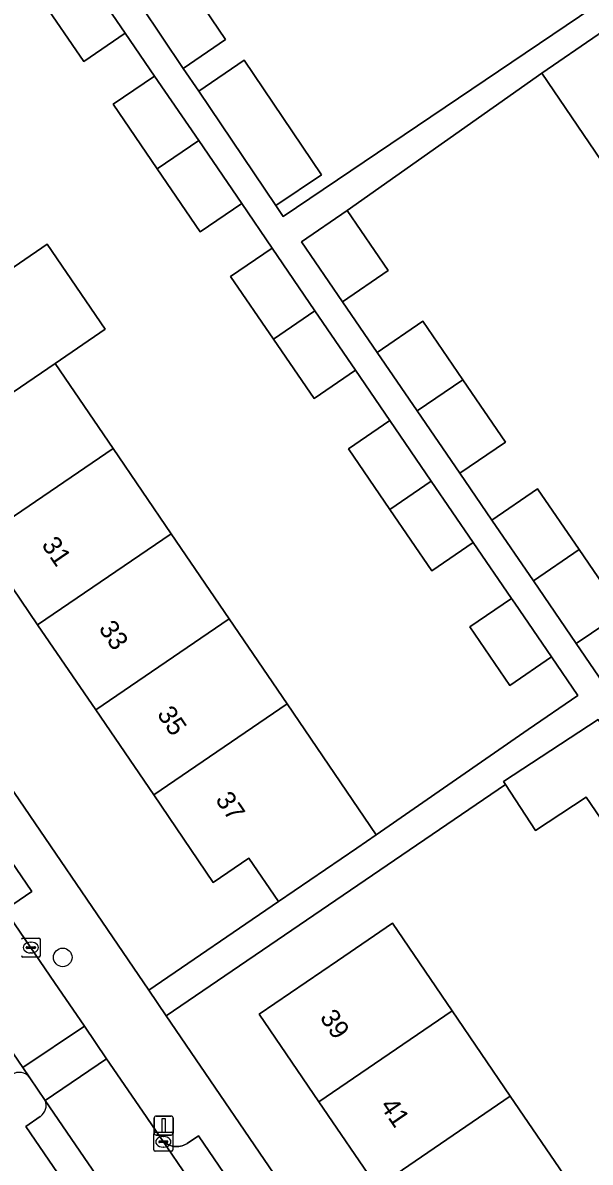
# Model space of a CAD drawing. Extents: x 157445 to 158888, y 383061 to 384688.
# Drawn here: x 158247.8 to 158277.7, y 383793.9 to 383854 of the extents above; entities that cross this region are included whole.
import ezdxf

# ---------------------------------------------------------------- set-up
doc = ezdxf.new("R2010")
doc.units = 0
for name, color, linetype in [('IMGEO_Boom', 7, 'Continuous'), ('IMGEO_Erf', 7, 'Continuous'), ('IMGEO_Kolk', 7, 'Continuous'), ('IMGEO_Lichtmast', 7, 'Continuous'), ('IMGEO_Pand', 7, 'Continuous'), ('IMGEO_Pand_nummerreeks', 7, 'Continuous'), ('IMGEO_Parkeervlak_open', 7, 'Continuous'), ('IMGEO_Rijbaan_lokaal_open', 7, 'Continuous'), ('IMGEO_Voetpad_open', 7, 'Continuous')]:
    doc.layers.add(name, color=color, linetype=linetype)

msp = doc.modelspace()

# ---------------------------------------------------------------- linework, layer by layer
at = {"layer": 'IMGEO_Boom'}
msp.add_circle((158249.88, 383804.706), 0.489, dxfattribs=at)
at = {"layer": 'IMGEO_Erf'}
for points in [[(158238.26, 383864.78), (158220.561, 383852.622), (158254.415, 383802.985), (158261.257, 383807.652), (158259.697, 383809.94), (158257.824, 383808.662), (158254.679, 383813.274), (158251.618, 383817.762), (158248.556, 383822.251), (158245.495, 383826.74), (158242.434, 383831.228), (158239.373, 383835.717), (158236.312, 383840.206), (158233.251, 383844.694), (158230.19, 383849.182), (158227.044, 383853.795), (158231.175, 383856.612)], [(158256.249, 383856.407), (158258.471, 383853.116), (158256.237, 383851.592), (158257.054, 383850.382), (158259.458, 383852.022), (158263.537, 383845.982), (158261.125, 383844.354), (158261.51, 383843.785), (158282.821, 383858.177)], [(158246.411, 383840.515), (158249.066, 383842.326), (158252.127, 383837.837), (158249.472, 383836.027), (158252.532, 383831.539), (158255.594, 383827.05), (158258.655, 383822.561), (158261.716, 383818.073), (158266.421, 383811.174), (158274.432, 383816.734), (158277.048, 383818.521), (158275.661, 383820.551), (158273.47, 383819.055), (158271.361, 383822.144), (158273.552, 383823.637), (158271.536, 383826.587), (158269.345, 383825.094), (158267.136, 383828.327), (158264.948, 383831.53), (158267.137, 383833.023), (158265.327, 383835.672), (158263.138, 383834.179), (158261, 383837.308), (158258.739, 383840.618), (158260.928, 383842.111), (158259.321, 383844.463), (158257.132, 383842.97), (158254.864, 383846.29), (158252.536, 383849.696), (158254.724, 383851.189), (158253.179, 383853.45), (158250.991, 383851.958), (158248.728, 383855.27)], [(158278.293, 383846.731), (158275.149, 383851.338), (158264.887, 383844.101), (158267.053, 383840.934), (158264.642, 383839.288), (158266.476, 383836.608), (158268.887, 383838.254), (158270.993, 383835.175), (158273.246, 383831.882), (158270.834, 383830.236), (158272.522, 383827.767), (158274.935, 383829.413), (158277.126, 383826.21), (158279.388, 383822.904), (158276.975, 383821.258), (158278.641, 383818.821)], [(158279.716, 383788.261), (158289.804, 383795.148), (158287.528, 383798.479), (158289.419, 383799.768), (158289.706, 383799.964), (158287.94, 383802.549), (158285.762, 383801.064), (158283.578, 383804.261), (158281.243, 383807.679), (158283.42, 383809.165), (158281.992, 383811.358), (158279.766, 383809.84), (158277.501, 383813.155), (158274.827, 383811.404), (158273.238, 383813.832), (158255.342, 383801.626), (158269.302, 383781.158)], [(158266.462, 383792.588), (158263.394, 383797.087), (158260.24, 383801.712), (158264.371, 383804.53), (158267.272, 383806.508), (158270.426, 383801.884), (158273.494, 383797.384), (158276.563, 383792.885)]]:
    msp.add_lwpolyline(points, dxfattribs=at)
at = {"layer": 'IMGEO_Kolk'}
for p, q in [((158247.772, 383805.725), (158248.624, 383805.725)), ((158248.185, 383805.505), (158248.21, 383805.505)), ((158248.698, 383805.651), (158248.698, 383804.799)), ((158248.624, 383804.725), (158247.772, 383804.725)), ((158247.956, 383805.219), (158247.956, 383805.231)), ((158248.394, 383805.182), (158247.996, 383805.182)), ((158247.999, 383805.268), (158248.397, 383805.268)), ((158248.208, 383804.945), (158248.183, 383804.945)), ((158248.44, 383805.231), (158248.44, 383805.219)), ((158254.687, 383794.556), (158254.687, 383795.408)), ((158254.762, 383795.482), (158255.614, 383795.482)), ((158255.175, 383795.262), (158255.2, 383795.262)), ((158255.688, 383795.408), (158255.688, 383794.556)), ((158254.946, 383794.976), (158254.946, 383794.988)), ((158255.384, 383794.939), (158254.986, 383794.939)), ((158254.989, 383795.025), (158255.387, 383795.025)), ((158255.198, 383794.702), (158255.173, 383794.702)), ((158255.43, 383794.988), (158255.43, 383794.976)), ((158255.614, 383794.482), (158254.762, 383794.482))]:
    msp.add_line(p, q, dxfattribs=at)
for points in [[(158247.772, 383805.725), (158248.624, 383805.725)], [(158248.698, 383805.651), (158248.698, 383804.799)], [(158248.624, 383804.725), (158247.772, 383804.725)], [(158254.687, 383794.556), (158254.687, 383795.408)], [(158254.762, 383795.482), (158255.614, 383795.482)], [(158255.688, 383795.408), (158255.688, 383794.556)], [(158255.614, 383794.482), (158254.762, 383794.482)]]:
    msp.add_lwpolyline(points, dxfattribs=at)
for centre, radius, start, end in [((158247.774, 383805.649), 0.0765, 91.55205, 178.44795), ((158247.774, 383805.649), 0.0765, 91.55205, 178.44795), ((158248.622, 383805.649), 0.0765, 1.55205, 88.44795), ((158248.622, 383805.649), 0.0765, 1.55205, 88.44795), ((158247.774, 383804.801), 0.0765, 181.55205, 268.44795), ((158247.774, 383804.801), 0.0765, 181.55205, 268.44795), ((158247.996, 383805.228), 0.0403, 85.87752, 175.75265), ((158247.993, 383805.218), 0.0366, 178.93798, 274.71019), ((158248.397, 383805.225), 0.043, 264.86636, 352.45326), ((158248.401, 383805.23), 0.0386, 1.73085, 96.63898), ((158248.622, 383804.801), 0.0765, 271.55205, 358.44795), ((158248.622, 383804.801), 0.0765, 271.55205, 358.44795), ((158254.764, 383795.406), 0.0765, 91.55205, 178.44795), ((158254.764, 383795.406), 0.0765, 91.55205, 178.44795), ((158255.612, 383795.406), 0.0765, 1.55205, 88.44795), ((158255.612, 383795.406), 0.0765, 1.55205, 88.44795), ((158254.764, 383794.558), 0.0765, 181.55205, 268.44795), ((158254.764, 383794.558), 0.0765, 181.55205, 268.44795), ((158254.986, 383794.985), 0.0403, 85.87752, 175.75265), ((158254.983, 383794.975), 0.0366, 178.93798, 274.71019), ((158255.387, 383794.982), 0.043, 264.86636, 352.45326), ((158255.391, 383794.987), 0.0386, 1.73085, 96.63898), ((158255.612, 383794.558), 0.0765, 271.55205, 358.44795), ((158255.612, 383794.558), 0.0765, 271.55205, 358.44795)]:
    msp.add_arc(centre, radius, start, end, dxfattribs=at)
for centre, major_axis, ratio, start_param, end_param in [((158248.184, 383805.225), (-0.387, 0.002), 0.722429, 4.712389, 7.853982), ((158248.209, 383805.225), (-0.39, 0.002), 0.717154, 1.570796, 4.712389), ((158255.174, 383794.982), (-0.387, 0.002), 0.722429, 4.712389, 7.853982), ((158255.199, 383794.982), (-0.39, 0.002), 0.717154, 1.570796, 4.712389)]:
    msp.add_ellipse(centre, major_axis=major_axis, ratio=ratio, start_param=start_param, end_param=end_param, dxfattribs=at)
at = {"layer": 'IMGEO_Lichtmast'}
for p, q in [((158254.809, 383796.34), (158255.599, 383796.34)), ((158255.599, 383796.34), (158254.809, 383796.34)), ((158254.709, 383795.44), (158254.709, 383796.24)), ((158254.709, 383796.24), (158254.709, 383795.44)), ((158255.699, 383796.24), (158255.699, 383795.44)), ((158255.699, 383795.44), (158255.699, 383796.24)), ((158255.599, 383795.34), (158254.809, 383795.34)), ((158254.809, 383795.34), (158255.599, 383795.34))]:
    msp.add_line(p, q, dxfattribs=at)
msp.add_lwpolyline([(158255.129, 383796.215), (158255.279, 383796.215), (158255.279, 383795.465), (158255.129, 383795.465), (158255.129, 383796.215)], dxfattribs=at)
for centre, start, end in [((158254.809, 383796.24), 90, 180), ((158254.809, 383796.24), 90, 180), ((158255.599, 383796.24), 0, 90), ((158255.599, 383796.24), 360, 90), ((158254.809, 383795.44), 180, 270), ((158254.809, 383795.44), 180, 270), ((158255.599, 383795.44), 270, 0), ((158255.599, 383795.44), 270, 0)]:
    msp.add_arc(centre, 0.1, start, end, dxfattribs=at)
at = {"layer": 'IMGEO_Pand'}
for points in [[(158250.916, 383856.762), (158248.728, 383855.27), (158250.991, 383851.958), (158253.179, 383853.45)], [(158256.249, 383856.407), (158254.015, 383854.882), (158256.237, 383851.592), (158258.471, 383853.116)], [(158278.293, 383846.731), (158285.41, 383851.588), (158282.267, 383856.195), (158278.137, 383853.377), (158275.149, 383851.338)], [(158259.458, 383852.022), (158257.054, 383850.382), (158261.125, 383844.354), (158263.537, 383845.982)], [(158254.724, 383851.189), (158252.536, 383849.696), (158254.864, 383846.29), (158257.052, 383847.782)], [(158257.052, 383847.782), (158254.864, 383846.29), (158257.132, 383842.97), (158259.321, 383844.463)], [(158264.887, 383844.101), (158262.478, 383842.453), (158264.642, 383839.288), (158267.053, 383840.934)], [(158252.127, 383837.837), (158249.066, 383842.326), (158246.411, 383840.515), (158239.373, 383835.717), (158242.434, 383831.228), (158249.472, 383836.027)], [(158260.928, 383842.111), (158258.739, 383840.618), (158261, 383837.308), (158263.189, 383838.801)], [(158263.189, 383838.801), (158261, 383837.308), (158263.138, 383834.179), (158265.327, 383835.672)], [(158266.476, 383836.608), (158268.581, 383833.529), (158270.993, 383835.175), (158268.887, 383838.254)], [(158249.472, 383836.027), (158242.434, 383831.228), (158245.495, 383826.74), (158252.532, 383831.539)], [(158270.993, 383835.175), (158268.581, 383833.529), (158270.834, 383830.236), (158273.246, 383831.882)], [(158267.137, 383833.023), (158264.948, 383831.53), (158267.136, 383828.327), (158269.326, 383829.821)], [(158252.532, 383831.539), (158245.495, 383826.74), (158248.556, 383822.251), (158255.594, 383827.05)], [(158269.326, 383829.821), (158267.136, 383828.327), (158269.345, 383825.094), (158271.536, 383826.587)], [(158272.522, 383827.767), (158274.713, 383824.564), (158277.126, 383826.21), (158274.935, 383829.413)], [(158255.594, 383827.05), (158248.556, 383822.251), (158251.618, 383817.762), (158258.655, 383822.561)], [(158277.126, 383826.21), (158274.713, 383824.564), (158276.975, 383821.258), (158279.388, 383822.904)], [(158273.728, 383823.38), (158273.552, 383823.637), (158271.361, 383822.144), (158273.47, 383819.055), (158275.661, 383820.551)], [(158254.679, 383813.274), (158261.716, 383818.073), (158258.655, 383822.561), (158251.618, 383817.762)], [(158254.679, 383813.274), (158257.824, 383808.662), (158259.697, 383809.94), (158261.257, 383807.652), (158265.388, 383810.47), (158266.421, 383811.174), (158261.716, 383818.073)], [(158273.136, 383813.988), (158273.238, 383813.832), (158274.827, 383811.404), (158277.501, 383813.155), (158279.766, 383809.84), (158281.992, 383811.358), (158278.13, 383817.257)], [(158270.426, 383801.884), (158267.272, 383806.508), (158264.371, 383804.53), (158260.24, 383801.712), (158263.394, 383797.087)], [(158266.462, 383792.588), (158273.494, 383797.384), (158270.426, 383801.884), (158263.394, 383797.087)], [(158269.531, 383788.089), (158276.563, 383792.885), (158273.494, 383797.384), (158266.462, 383792.588)]]:
    msp.add_lwpolyline(points, close=True, dxfattribs=at)
at = {"layer": 'IMGEO_Parkeervlak_open'}
for points in [[(158248.151, 383798.359), (158247.776, 383798.907), (158231.849, 383822.216)], [(158247.246, 383807.504), (158248.248, 383808.187), (158238.955, 383821.804)], [(158262.112, 383777.939), (158248.949, 383797.166)], [(158248.698, 383796.319), (158247.928, 383795.793), (158260.491, 383777.419), (158261.427, 383778.057)], [(158266.338, 383781.661), (158257.041, 383795.301), (158256.452, 383794.9), (158256.422, 383794.88), (158256.344, 383794.836), (158256.263, 383794.799), (158256.179, 383794.769), (158256.092, 383794.747), (158256.003, 383794.733), (158255.914, 383794.726), (158255.825, 383794.728), (158255.736, 383794.738), (158255.648, 383794.755), (158255.562, 383794.78), (158255.479, 383794.813), (158255.399, 383794.854), (158255.323, 383794.901), (158255.251, 383794.955), (158255.185, 383795.014), (158255.124, 383795.08), (158255.069, 383795.151), (158265.297, 383780.146)]]:
    msp.add_lwpolyline(points, dxfattribs=at)
for centre, radius, start, end in [((158247.587, 383797.943), 0.701, 36.41426, 124.29313), ((158248.303, 383796.897), 0.7, 304.37226, 22.61441)]:
    msp.add_arc(centre, radius, start, end, dxfattribs=at)
at = {"layer": 'IMGEO_Rijbaan_lokaal_open'}
for points in [[(158247.776, 383798.907), (158251.028, 383801.074), (158249.448, 383803.39), (158247.114, 383806.809), (158237.215, 383821.317), (158236.772, 383821.968), (158235.678, 383823.579), (158234.672, 383825.051), (158231.411, 383822.857), (158231.849, 383822.216)], [(158248.151, 383798.359), (158248.949, 383797.166), (158252.196, 383799.363), (158251.028, 383801.074), (158247.776, 383798.907)], [(158255.069, 383795.151), (158254.082, 383796.598), (158252.196, 383799.363), (158248.949, 383797.166), (158262.112, 383777.939), (158264.308, 383774.728), (158266.276, 383771.893), (158272.742, 383762.581), (158273.097, 383762.835), (158273.675, 383762.423), (158275.936, 383765.242), (158275.19, 383765.845), (158274.521, 383766.556), (158274.182, 383767.055), (158267.164, 383777.394), (158265.304, 383780.135), (158265.297, 383780.146)]]:
    msp.add_lwpolyline(points, close=True, dxfattribs=at)
at = {"layer": 'IMGEO_Voetpad_open'}
for points in [[(158282.821, 383858.177), (158261.51, 383843.785), (158261.125, 383844.354), (158257.054, 383850.382), (158256.237, 383851.592), (158254.015, 383854.882)], [(158250.916, 383856.762), (158253.179, 383853.45), (158254.724, 383851.189), (158257.052, 383847.782), (158259.321, 383844.463), (158260.928, 383842.111), (158263.189, 383838.801), (158265.327, 383835.672), (158267.137, 383833.023), (158269.326, 383829.821), (158271.536, 383826.587), (158273.552, 383823.637), (158273.728, 383823.38), (158275.661, 383820.551), (158277.048, 383818.521), (158274.432, 383816.734), (158266.421, 383811.174), (158265.388, 383810.47), (158261.257, 383807.652), (158254.415, 383802.985), (158255.342, 383801.626), (158273.238, 383813.832), (158273.136, 383813.988), (158278.13, 383817.257)], [(158278.641, 383818.821), (158276.975, 383821.258), (158274.713, 383824.564), (158272.522, 383827.767), (158270.834, 383830.236), (158268.581, 383833.529), (158266.476, 383836.608), (158264.642, 383839.288), (158262.478, 383842.453), (158264.887, 383844.101), (158275.149, 383851.338), (158278.137, 383853.377)], [(158269.302, 383781.158), (158255.342, 383801.626), (158254.415, 383802.985), (158220.561, 383852.622)], [(158238.955, 383821.804), (158248.248, 383808.187), (158247.246, 383807.504)], [(158247.114, 383806.809), (158249.448, 383803.39), (158251.028, 383801.074), (158252.196, 383799.363), (158254.082, 383796.598), (158255.069, 383795.151), (158255.124, 383795.08), (158255.185, 383795.014), (158255.251, 383794.955), (158255.323, 383794.901), (158255.399, 383794.854), (158255.479, 383794.813), (158255.562, 383794.78), (158255.648, 383794.755), (158255.736, 383794.738), (158255.825, 383794.728), (158255.914, 383794.726), (158256.003, 383794.733), (158256.092, 383794.747), (158256.179, 383794.769), (158256.263, 383794.799), (158256.344, 383794.836), (158256.422, 383794.88), (158256.452, 383794.9), (158257.041, 383795.301), (158266.338, 383781.661)], [(158248.949, 383797.166), (158248.151, 383798.359)], [(158261.427, 383778.057), (158260.491, 383777.419), (158247.928, 383795.793), (158248.698, 383796.319)]]:
    msp.add_lwpolyline(points, dxfattribs=at)
for centre, radius, start, end in [((158247.587, 383797.943), 0.701, 36.41426, 124.29313), ((158248.303, 383796.897), 0.7, 304.37226, 22.61441)]:
    msp.add_arc(centre, radius, start, end, dxfattribs=at)

# ---------------------------------------------------------------- texts
at = {"layer": 'IMGEO_Pand_nummerreeks'}
for s, rotation, p in [('31', 304.29131, (158248.731, 383826.467)), ('33', 304.29337, (158251.745, 383822.047)), ('35', 304.29337, (158254.823, 383817.534)), ('37', 304.29337, (158257.901, 383813.021)), ('39', 304.29301, (158263.411, 383801.533)), ('41', 304.29301, (158266.586, 383796.878))]:
    msp.add_text(s, height=1, rotation=rotation, dxfattribs=at).set_placement(p)

doc.saveas('drawing.dxf')
